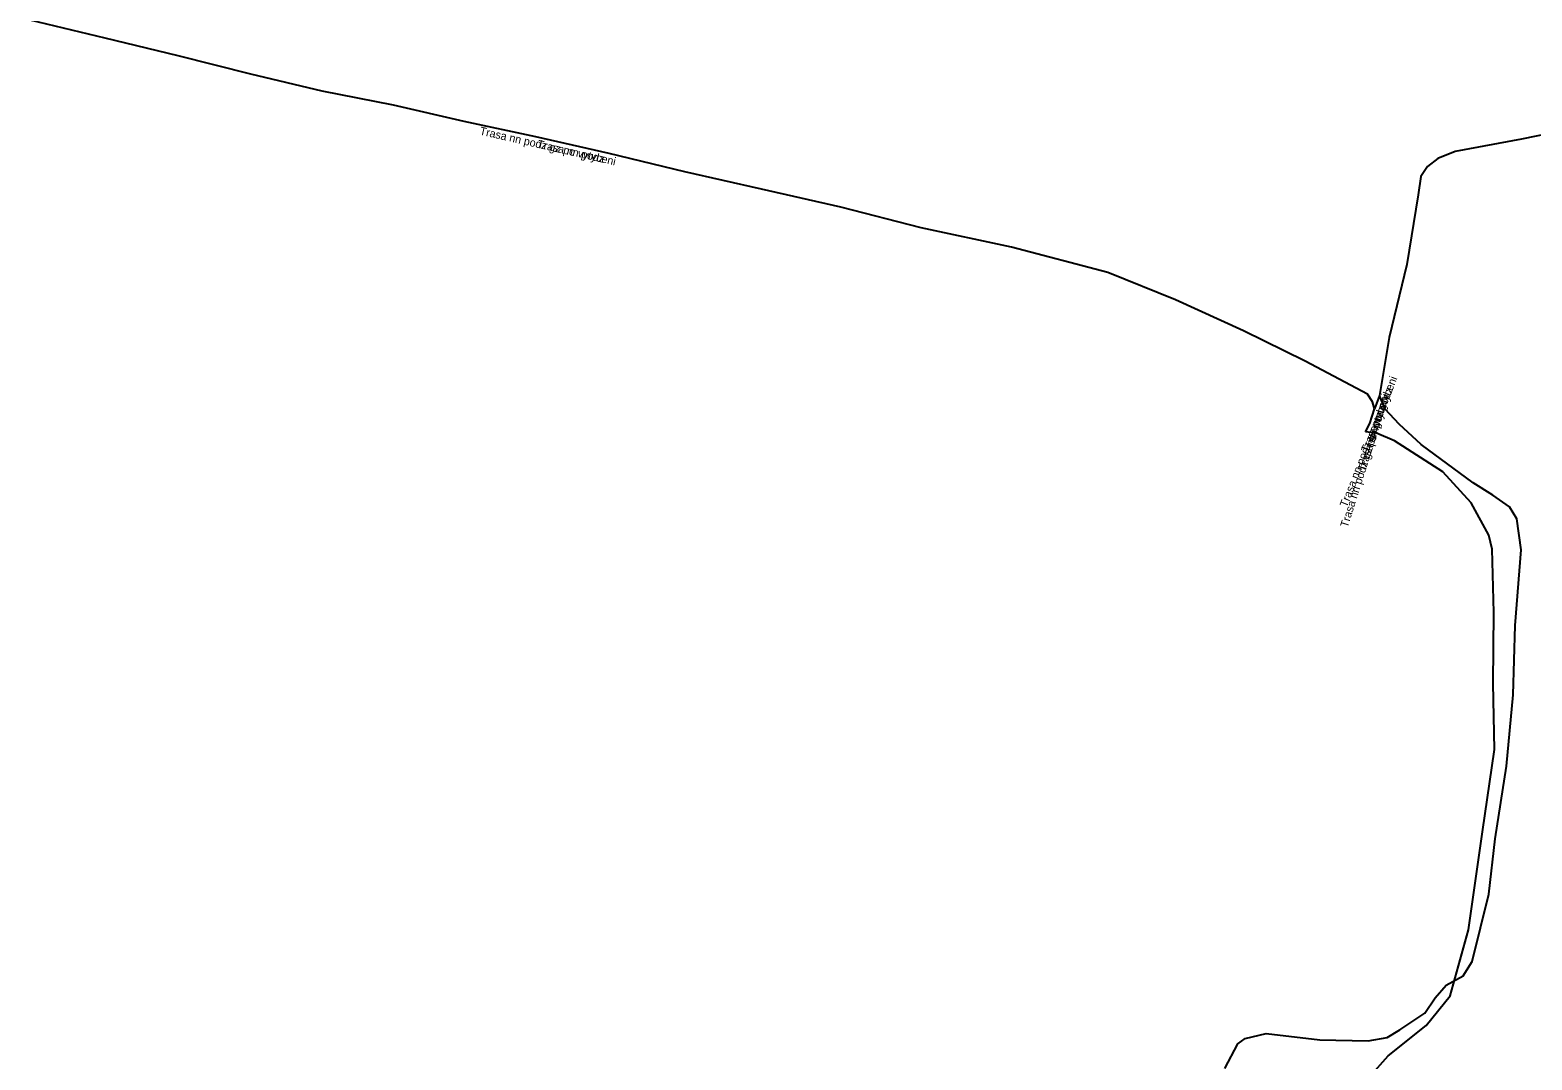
# Model space of a CAD drawing. Extents: x -817778 to -817398, y -1067927 to -1067625.
# Drawn here: x -817682.2 to -817588.3, y -1067862.5 to -1067798.2 of the extents above; entities that cross this region are included whole.
import ezdxf

# ---------------------------------------------------------------- set-up
doc = ezdxf.new("R2010")
doc.units = 0
doc.layers.add('Popiskový text - Ostatní atributy Trasy', color=7, linetype='Continuous')
doc.layers.add('Spojnice NN', color=7, linetype='Continuous')

msp = doc.modelspace()

# ---------------------------------------------------------------- linework, layer by layer
at = {"layer": 'Spojnice NN'}
for points in [[(-817598.19, -1067821.81), (-817598.3, -1067821.39), (-817598.61, -1067820.91), (-817602.52, -1067818.84), (-817606.37, -1067816.94), (-817610.62, -1067815.01), (-817614.85, -1067813.31), (-817620.86, -1067811.72), (-817626.52, -1067810.51), (-817631.54, -1067809.22), (-817636.49, -1067808.1), (-817641.29, -1067807.02), (-817646, -1067805.87), (-817650.59, -1067804.82), (-817655.08, -1067803.87), (-817659.48, -1067802.84), (-817663.95, -1067801.97), (-817668.41, -1067800.91), (-817672.94, -1067799.77), (-817677.5, -1067798.67), (-817682.2, -1067797.54)], [(-817598.19, -1067821.81), (-817598.3, -1067821.39), (-817598.61, -1067820.91), (-817602.52, -1067818.84), (-817606.37, -1067816.94), (-817610.62, -1067815.01), (-817614.85, -1067813.31), (-817620.86, -1067811.72), (-817626.52, -1067810.51), (-817631.54, -1067809.22), (-817636.49, -1067808.1), (-817641.29, -1067807.02), (-817646, -1067805.87), (-817650.59, -1067804.82), (-817655.08, -1067803.87), (-817659.48, -1067802.84), (-817663.95, -1067801.97), (-817668.41, -1067800.91), (-817672.94, -1067799.77), (-817677.5, -1067798.67), (-817682.2, -1067797.54)], [(-817552.43, -1067809.23), (-817553.23, -1067809.5), (-817557.63, -1067808.3), (-817562.23, -1067806.82), (-817566.44, -1067805.62), (-817570.96, -1067804.92), (-817575.37, -1067804.46), (-817580.18, -1067803.96), (-817584.51, -1067804.06), (-817589, -1067804.97), (-817593.13, -1067805.75), (-817594.22, -1067806.17), (-817594.86, -1067806.67), (-817595.28, -1067807.3), (-817595.46, -1067808.44), (-817596.15, -1067812.8), (-817597.27, -1067817.36), (-817597.87, -1067820.99)], [(-817552.43, -1067809.23), (-817553.23, -1067809.5), (-817557.63, -1067808.3), (-817562.23, -1067806.82), (-817566.44, -1067805.62), (-817570.96, -1067804.92), (-817575.37, -1067804.46), (-817580.18, -1067803.96), (-817584.51, -1067804.06), (-817589, -1067804.97), (-817593.13, -1067805.75), (-817594.22, -1067806.17), (-817594.86, -1067806.67), (-817595.28, -1067807.3), (-817595.46, -1067808.44), (-817596.15, -1067812.8), (-817597.27, -1067817.36), (-817597.87, -1067820.99)], [(-817607.54, -1067863.03), (-817606.72, -1067861.49), (-817606.26, -1067861.16), (-817604.95, -1067860.84), (-817601.59, -1067861.23), (-817598.57, -1067861.3), (-817597.39, -1067861.09), (-817596.6, -1067860.61), (-817595.04, -1067859.58), (-817594.39, -1067858.62), (-817593.71, -1067857.83), (-817592.63, -1067857.23), (-817592.07, -1067856.35), (-817591.04, -1067852.13), (-817590.63, -1067848.67), (-817589.94, -1067844.14), (-817589.51, -1067839.69), (-817589.39, -1067835.35), (-817589.02, -1067830.62), (-817589.29, -1067828.68), (-817589.75, -1067827.94), (-817590.79, -1067827.22), (-817592.02, -1067826.43), (-817595.26, -1067824.05), (-817596.63, -1067822.77), (-817597.51, -1067821.84), (-817597.87, -1067820.99)], [(-817607.54, -1067863.03), (-817606.72, -1067861.49), (-817606.26, -1067861.16), (-817604.95, -1067860.84), (-817601.59, -1067861.23), (-817598.57, -1067861.3), (-817597.39, -1067861.09), (-817596.6, -1067860.61), (-817595.04, -1067859.58), (-817594.39, -1067858.62), (-817593.71, -1067857.83), (-817592.63, -1067857.23), (-817592.07, -1067856.35), (-817591.04, -1067852.13), (-817590.63, -1067848.67), (-817589.94, -1067844.14), (-817589.51, -1067839.69), (-817589.39, -1067835.35), (-817589.02, -1067830.62), (-817589.29, -1067828.68), (-817589.75, -1067827.94), (-817590.79, -1067827.22), (-817592.02, -1067826.43), (-817595.26, -1067824.05), (-817596.63, -1067822.77), (-817597.51, -1067821.84), (-817597.87, -1067820.99)], [(-817597.87, -1067820.99), (-817598.19, -1067821.81)], [(-817597.87, -1067820.99), (-817598.19, -1067821.81)], [(-817598.75, -1067823.26), (-817598.48, -1067822.73), (-817598.19, -1067821.81)], [(-817598.75, -1067823.26), (-817598.48, -1067822.73), (-817598.19, -1067821.81)], [(-817599.61, -1067864.81), (-817597.33, -1067862.24), (-817594.96, -1067860.33), (-817593.46, -1067858.49), (-817592.3, -1067854.37), (-817591.44, -1067848.24), (-817590.68, -1067843.09), (-817590.76, -1067838.97), (-817590.73, -1067834.54), (-817590.83, -1067830.59), (-817591.04, -1067829.71), (-817592.13, -1067827.69), (-817593.9, -1067825.76), (-817596.94, -1067823.81), (-817598.06, -1067823.33), (-817598.75, -1067823.26)], [(-817599.61, -1067864.81), (-817597.33, -1067862.24), (-817594.96, -1067860.33), (-817593.46, -1067858.49), (-817592.3, -1067854.37), (-817591.44, -1067848.24), (-817590.68, -1067843.09), (-817590.76, -1067838.97), (-817590.73, -1067834.54), (-817590.83, -1067830.59), (-817591.04, -1067829.71), (-817592.13, -1067827.69), (-817593.9, -1067825.76), (-817596.94, -1067823.81), (-817598.06, -1067823.33), (-817598.75, -1067823.26)]]:
    msp.add_lwpolyline(points, dxfattribs=at)

# ---------------------------------------------------------------- texts
at = {"layer": 'Popiskový text - Ostatní atributy Trasy'}
for s, rotation, p in [('Trasa nn podz gz po vytyceni', 347.11483, (-817654.132, -1067804.676)), ('Trasa nn podz', 347.11483, (-817650.54, -1067805.498)), ('Trasa nn podz gz po vytyceni', 68.68209, (-817599.908, -1067828.001)), ('Trasa nn podz gz po vytyceni', 72.50424, (-817599.859, -1067829.266)), ('Trasa nn podz', 68.68209, (-817598.568, -1067824.568)), ('Trasa nn podz', 72.50424, (-817598.751, -1067825.751))]:
    msp.add_text(s, height=0.5, rotation=rotation, dxfattribs=at).set_placement(p)

doc.saveas('drawing.dxf')
